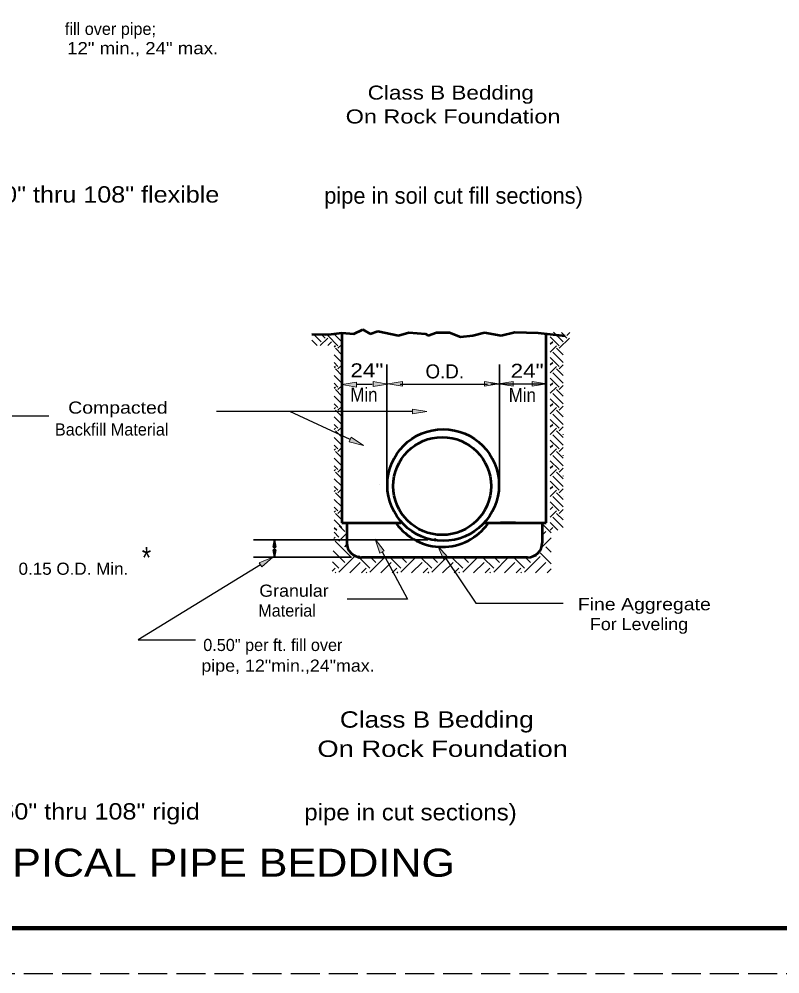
# Model space of a CAD drawing. Extents: x 36.1 to 71.5, y 0.2 to 22.2.
# Drawn here: x 44.21 to 52.56, y 0.21 to 10.68 of the extents above; entities that cross this region are included whole.
import ezdxf

# ---------------------------------------------------------------- set-up
doc = ezdxf.new("R2010")
doc.units = 0
doc.header["$LTSCALE"] = 0.053
doc.header["$PDMODE"] = 32
doc.header["$PDSIZE"] = 0.0265
doc.linetypes.add('LONG_DASHED', pattern=[7.5, 6, -1.5])
for name, color, linetype, lineweight in [('1', 7, 'Continuous', 35), ('3', 7, 'Continuous', 25), ('4', 7, 'Continuous', 35), ('6', 7, 'Continuous', 13)]:
    doc.layers.add(name, color=color, linetype=linetype, lineweight=lineweight)

msp = doc.modelspace()

# ---------------------------------------------------------------- hatches: boundary and pattern name
at = {"layer": '1'}
for points in [[(47.91383, 6.64717), (47.91383, 6.7005), (47.75383, 6.67383), (47.75383, 6.67383)], [(48.0985, 6.65275), (48.0985, 6.70608), (48.2585, 6.67942), (48.2585, 6.67942)], [(48.4185, 6.65508), (48.4185, 6.7085), (48.2585, 6.68183), (48.2585, 6.68183)], [(49.31708, 6.65508), (49.31708, 6.7085), (49.47708, 6.68183), (49.47708, 6.68183)], [(47.02833, 4.89192), (47.00167, 4.89192), (47.015, 4.97192), (47.015, 4.97192)], [(47.02833, 4.86225), (47.00167, 4.86225), (47.015, 4.78225), (47.015, 4.78225)]]:
    msp.add_hatch(color=256, dxfattribs=at).paths.add_polyline_path(points)
at = {"layer": '3'}
for points in [[(49.63242, 6.65633), (49.63242, 6.70967), (49.47242, 6.683), (49.47242, 6.683)], [(49.84042, 6.65633), (49.84042, 6.70967), (50.00042, 6.683), (50.00042, 6.683)], [(48.52717, 6.40533), (48.52717, 6.35192), (48.68717, 6.37867), (48.68717, 6.37867)], [(47.85717, 6.096), (47.83475, 6.04783), (47.99117, 6.00458), (47.99117, 6.00458)], [(48.17117, 4.827), (48.218, 4.85242), (48.1185, 4.9805), (48.1185, 4.9805)], [(48.87183, 4.75342), (48.91625, 4.78308), (48.80533, 4.90133), (48.80533, 4.90133)], [(46.84783, 4.72108), (46.87558, 4.67575), (46.99808, 4.78225), (46.99808, 4.78225)]]:
    msp.add_hatch(color=256, dxfattribs=at).paths.add_polyline_path(points)

# ---------------------------------------------------------------- linework, layer by layer
at = {"layer": '1', "lineweight": 53}
for p, q in [((47.42317, 7.225), (47.6065, 7.22233)), ((47.6065, 7.22233), (47.75383, 7.2425)), ((47.75383, 7.2425), (47.88425, 7.22883)), ((47.75383, 7.2425), (47.75383, 5.15825)), ((47.88425, 7.22883), (47.9825, 7.27642)), ((47.9825, 7.27642), (48.06558, 7.22883)), ((48.06558, 7.22883), (48.14867, 7.2605)), ((48.14867, 7.2605), (48.37533, 7.21292)), ((48.37533, 7.21292), (48.48875, 7.24458)), ((48.48875, 7.24458), (48.67008, 7.22883)), ((48.67008, 7.22883), (48.70025, 7.21292)), ((48.70025, 7.21292), (48.79092, 7.24458)), ((48.79092, 7.24458), (48.9345, 7.24458)), ((48.9345, 7.24458), (49.05533, 7.197)), ((49.19133, 7.21292), (49.31983, 7.24458)), ((49.31983, 7.24458), (49.50117, 7.21292)), ((49.50117, 7.21292), (49.65067, 7.24925)), ((49.65067, 7.24925), (49.907, 7.2425)), ((49.907, 7.2425), (50.20183, 7.20892)), ((49.99633, 5.15825), (49.99633, 7.23225)), ((49.05533, 7.197), (49.19133, 7.21292)), ((47.75383, 5.15825), (48.39975, 5.15825)), ((47.80833, 5.15825), (47.80833, 4.93975)), ((49.31333, 5.15825), (49.99633, 5.15825)), ((49.6585, 5.15825), (49.4935, 5.15825)), ((49.95133, 5.15825), (49.95133, 4.93975)), ((49.79133, 4.77975), (47.96833, 4.77975))]:
    msp.add_line(p, q, dxfattribs=at)
at = {"layer": '1'}
for p, q in [((48.24733, 5.64717), (48.24733, 6.8955)), ((49.48267, 5.64725), (49.48267, 6.89558)), ((50.04892, 5.04983), (49.95133, 5.14742)), ((47.72192, 5.001), (47.66817, 5.05475)), ((47.72192, 4.95858), (47.80833, 5.04492)), ((47.78558, 5.06467), (47.72458, 5.12558)), ((49.95133, 5.02425), (49.99183, 5.06467)), ((48.69583, 4.97192), (46.78458, 4.97192)), ((47.66492, 4.98633), (47.6795, 5.001)), ((47.84925, 4.78883), (47.6795, 4.95858)), ((49.94292, 4.88858), (50.04892, 4.99458)), ((47.015, 4.89192), (47.015, 4.86225)), ((47.78558, 4.72525), (47.6585, 4.85225)), ((47.78558, 4.89492), (47.80967, 4.91908)), ((47.84925, 4.83125), (47.85, 4.832)), ((50.04892, 4.71042), (49.92808, 4.83125)), ((50.04892, 4.83767), (49.99183, 4.89492)), ((47.86083, 4.78225), (46.78458, 4.78225)), ((47.72192, 4.66158), (47.65283, 4.73083)), ((47.72192, 4.61917), (47.89158, 4.78883)), ((47.84058, 4.61058), (47.95525, 4.72525)), ((48.06133, 4.66158), (47.94083, 4.78225)), ((48.06133, 4.61917), (48.22192, 4.77975)), ((48.125, 4.72525), (48.07042, 4.77975)), ((48.18008, 4.61058), (48.29475, 4.72525)), ((48.40075, 4.66158), (48.2825, 4.77975)), ((48.40075, 4.61917), (48.56142, 4.77975)), ((48.46442, 4.72525), (48.40983, 4.77975)), ((48.5195, 4.61058), (48.63417, 4.72525)), ((48.74017, 4.66158), (48.62192, 4.77975)), ((48.74017, 4.61917), (48.90083, 4.77975)), ((48.80383, 4.72525), (48.74917, 4.77975)), ((48.85883, 4.61058), (48.9735, 4.72525)), ((49.0795, 4.66158), (48.96142, 4.77975)), ((49.0795, 4.61917), (49.24017, 4.77975)), ((49.14325, 4.72525), (49.08858, 4.77975)), ((49.19825, 4.61058), (49.31292, 4.72525)), ((49.419, 4.66158), (49.30083, 4.77975)), ((49.419, 4.61917), (49.57958, 4.77975)), ((49.48267, 4.72525), (49.42808, 4.77975)), ((49.53767, 4.61058), (49.65233, 4.72525)), ((49.75842, 4.66158), (49.64017, 4.77975)), ((49.75842, 4.61917), (49.92808, 4.78883)), ((49.82208, 4.72525), (49.7675, 4.77975)), ((49.88567, 4.78883), (49.87258, 4.80192)), ((49.87717, 4.61058), (49.99183, 4.72525)), ((47.648, 4.63008), (47.6795, 4.66158)), ((47.68808, 4.61058), (47.6795, 4.61917)), ((47.96783, 4.61058), (48.019, 4.66158)), ((48.0275, 4.61058), (48.019, 4.61917)), ((48.30725, 4.61058), (48.35842, 4.66158)), ((48.36692, 4.61058), (48.35842, 4.61917)), ((48.64675, 4.61058), (48.69767, 4.66158)), ((48.70633, 4.61058), (48.69767, 4.61917)), ((48.98617, 4.61058), (49.03717, 4.66158)), ((49.04575, 4.61058), (49.03717, 4.61917)), ((49.3255, 4.61058), (49.3765, 4.66158)), ((49.38517, 4.61058), (49.3765, 4.61917)), ((49.66492, 4.61058), (49.71592, 4.66158)), ((49.72458, 4.61058), (49.71592, 4.61917)), ((50.00433, 4.61058), (50.04892, 4.65517))]:
    msp.add_line(p, q, dxfattribs=at)
at = {"layer": '1', "lineweight": 13}
msp.add_line((47.75383, 6.60183), (47.75383, 6.44342), dxfattribs=at)
at = {"layer": '1', "lineweight": 25}
for p, q in [((48.08758, 6.67383), (47.91383, 6.67383)), ((48.39417, 6.67683), (49.353, 6.67683))]:
    msp.add_line(p, q, dxfattribs=at)
at = {"layer": '1', "linetype": 'LONG_DASHED', "lineweight": 25}
msp.add_line((71.33717, 0.21317), (36.13717, 0.21317), dxfattribs=at)
at = {"layer": '1', "lineweight": 158}
msp.add_lwpolyline([(71.25383, 21.71317), (71.25383, 0.71317), (38.75383, 0.71317)], dxfattribs=at)
at = {"layer": '1', "lineweight": 13}
for points in [[(47.91383, 6.64717), (47.91383, 6.7005), (47.75383, 6.67383), (47.75383, 6.67383)], [(48.0985, 6.65275), (48.0985, 6.70608), (48.2585, 6.67942), (48.2585, 6.67942)], [(48.4185, 6.65508), (48.4185, 6.7085), (48.2585, 6.68183), (48.2585, 6.68183)], [(49.31708, 6.65508), (49.31708, 6.7085), (49.47708, 6.68183), (49.47708, 6.68183)]]:
    msp.add_lwpolyline(points, close=True, dxfattribs=at)
at = {"layer": '1'}
for points in [[(47.02833, 4.89192), (47.00167, 4.89192), (47.015, 4.97192), (47.015, 4.97192)], [(47.02833, 4.86225), (47.00167, 4.86225), (47.015, 4.78225), (47.015, 4.78225)]]:
    msp.add_lwpolyline(points, close=True, dxfattribs=at)
at = {"layer": '1', "lineweight": 53}
for centre, radius in [((48.86494, 5.57276), 0.61202), ((48.85386, 5.56167), 0.53646)]:
    msp.add_circle(centre, radius, dxfattribs=at)
for centre, radius, start, end in [((48.85464, 5.51487), 0.6208, 215.70389, 324.29611), ((47.96831, 4.93976), 0.16, 180, 270), ((49.79135, 4.93976), 0.16, 270, 0)]:
    msp.add_arc(centre, radius, start, end, dxfattribs=at)
at = {"layer": '3'}
for p, q in [((49.38783, 6.68233), (49.99633, 6.68233)), ((43.22292, 6.33283), (44.53925, 6.33283)), ((48.52717, 6.37867), (46.3785, 6.37867)), ((47.84592, 6.07192), (47.18475, 6.37867))]:
    msp.add_line(p, q, dxfattribs=at)
at = {"layer": '3', "lineweight": 13}
msp.add_line((49.65067, 6.67383), (49.65075, 6.67383), dxfattribs=at)
for points in [[(49.63242, 6.65633), (49.63242, 6.70967), (49.47242, 6.683), (49.47242, 6.683)], [(49.84042, 6.65633), (49.84042, 6.70967), (50.00042, 6.683), (50.00042, 6.683)], [(48.52717, 6.40533), (48.52717, 6.35192), (48.68717, 6.37867), (48.68717, 6.37867)], [(47.85717, 6.096), (47.83475, 6.04783), (47.99117, 6.00458), (47.99117, 6.00458)], [(48.17117, 4.827), (48.218, 4.85242), (48.1185, 4.9805), (48.1185, 4.9805)], [(48.87183, 4.75342), (48.91625, 4.78308), (48.80533, 4.90133), (48.80533, 4.90133)], [(46.84783, 4.72108), (46.87558, 4.67575), (46.99808, 4.78225), (46.99808, 4.78225)]]:
    msp.add_lwpolyline(points, close=True, dxfattribs=at)
at = {"layer": '3'}
for points in [[(48.19467, 4.83967), (48.475, 4.32142), (47.81283, 4.32142)], [(48.89408, 4.76825), (49.22192, 4.27692), (50.18117, 4.27692)], [(46.86167, 4.6985), (45.52125, 3.87625), (46.14933, 3.87625)]]:
    msp.add_lwpolyline(points, dxfattribs=at)
at = {"layer": '4'}
for p, q in [((47.52783, 7.14242), (47.4455, 7.22467)), ((47.57017, 7.18475), (47.53158, 7.22342)), ((47.75383, 7.14258), (47.666, 7.23042)), ((50.18017, 7.14242), (50.07417, 7.24833)), ((50.2225, 7.18475), (50.16125, 7.246)), ((50.2225, 7.213), (50.253, 7.24367)), ((47.48408, 7.10125), (47.42317, 7.16217)), ((47.515, 7.10125), (47.5985, 7.18475)), ((47.71167, 7.09992), (47.5985, 7.213)), ((47.59983, 7.10125), (47.64092, 7.14242)), ((50.13767, 7.09992), (50.04017, 7.19733)), ((50.04017, 7.11567), (50.067, 7.14242)), ((50.13767, 7.07167), (50.25075, 7.18475)), ((47.6705, 7.08717), (47.68325, 7.09992)), ((47.75383, 7.00125), (47.68325, 7.07167)), ((47.71167, 7.07167), (47.75383, 7.11383)), ((50.04017, 7.03075), (50.10942, 7.09992)), ((50.18017, 6.91608), (50.067, 7.02925)), ((50.18117, 6.99983), (50.10942, 7.07167)), ((50.18017, 7.02925), (50.18117, 7.03033)), ((47.75383, 6.91625), (47.6705, 6.99958)), ((47.71167, 6.87375), (47.6705, 6.91483)), ((50.13767, 6.87375), (50.04017, 6.97117)), ((50.04017, 6.88942), (50.067, 6.91608)), ((47.6705, 6.86083), (47.68325, 6.87375)), ((47.75383, 6.77492), (47.68325, 6.84533)), ((47.71167, 6.84533), (47.75383, 6.88758)), ((50.04017, 6.8045), (50.10942, 6.87375)), ((50.18117, 6.77358), (50.10942, 6.84533)), ((50.13767, 6.84533), (50.18117, 6.88892)), ((47.75383, 6.69008), (47.6705, 6.77333)), ((50.13767, 6.64742), (50.04017, 6.74492)), ((50.18017, 6.68983), (50.067, 6.803)), ((47.71167, 6.64742), (47.6705, 6.6885)), ((47.6705, 6.63458), (47.68325, 6.64742)), ((47.75383, 6.54858), (47.68325, 6.61917)), ((47.71167, 6.61917), (47.75383, 6.66133)), ((50.04017, 6.66308), (50.067, 6.68983)), ((50.04017, 6.57825), (50.10942, 6.64742)), ((50.18117, 6.54733), (50.10942, 6.61917)), ((50.13767, 6.61917), (50.18117, 6.66258)), ((47.75383, 6.46383), (47.6705, 6.54717)), ((50.13767, 6.42117), (50.04017, 6.51858)), ((50.18017, 6.46358), (50.067, 6.57667)), ((50.18017, 6.57667), (50.18117, 6.57783)), ((47.71167, 6.42117), (47.6705, 6.46225)), ((47.6705, 6.40833), (47.68325, 6.42117)), ((47.75383, 6.32233), (47.68325, 6.39292)), ((47.71167, 6.39292), (47.75383, 6.435)), ((50.04017, 6.43683), (50.067, 6.46358)), ((50.04017, 6.35192), (50.10942, 6.42117)), ((50.18117, 6.321), (50.10942, 6.39292)), ((50.13767, 6.39292), (50.18117, 6.43642)), ((47.75383, 6.2375), (47.6705, 6.32075)), ((50.13767, 6.19492), (50.04017, 6.29225)), ((50.18017, 6.23725), (50.067, 6.35042)), ((47.71167, 6.19492), (47.6705, 6.23592)), ((47.6705, 6.182), (47.68325, 6.19492)), ((47.71167, 6.16658), (47.75383, 6.20875)), ((50.04017, 6.21058), (50.067, 6.23725)), ((50.04017, 6.12567), (50.10942, 6.19492)), ((50.13767, 6.16658), (50.18117, 6.21017)), ((47.75383, 6.01125), (47.6705, 6.09458)), ((47.75383, 6.096), (47.68325, 6.16658)), ((50.18017, 6.011), (50.067, 6.12425)), ((50.18117, 6.09475), (50.10942, 6.16658)), ((50.18017, 6.12425), (50.18117, 6.12525)), ((47.71167, 5.96858), (47.6705, 6.00958)), ((47.6705, 5.95575), (47.68325, 5.96858)), ((47.71167, 5.94025), (47.75383, 5.98258)), ((50.13767, 5.96858), (50.04017, 6.06608)), ((50.04017, 5.98425), (50.067, 6.011)), ((50.04017, 5.89942), (50.10942, 5.96858)), ((50.13767, 5.94025), (50.18117, 5.98383)), ((47.75383, 5.785), (47.6705, 5.86825)), ((47.75383, 5.86983), (47.68325, 5.94025)), ((50.18017, 5.78475), (50.067, 5.89783)), ((50.18117, 5.8685), (50.10942, 5.94025)), ((50.18017, 5.89783), (50.18117, 5.899)), ((47.71167, 5.74233), (47.6705, 5.78342)), ((50.13767, 5.74233), (50.04017, 5.83967)), ((50.04017, 5.758), (50.067, 5.78475)), ((50.13767, 5.71408), (50.18117, 5.75758)), ((47.6705, 5.72958), (47.68325, 5.74233)), ((47.75383, 5.64358), (47.68325, 5.71408)), ((47.71167, 5.71408), (47.75383, 5.75625)), ((50.04017, 5.67325), (50.10942, 5.74233)), ((50.18017, 5.55842), (50.067, 5.67158)), ((50.18117, 5.64217), (50.10942, 5.71408)), ((50.18017, 5.67158), (50.18117, 5.67267)), ((47.75383, 5.55858), (47.6705, 5.64192)), ((47.71167, 5.51608), (47.6705, 5.55717)), ((50.13767, 5.51608), (50.04017, 5.6135)), ((50.04017, 5.53175), (50.067, 5.55842)), ((47.6705, 5.50325), (47.68325, 5.51608)), ((47.75383, 5.41725), (47.68325, 5.48767)), ((47.71167, 5.48767), (47.75383, 5.52992)), ((50.04017, 5.44692), (50.10942, 5.51608)), ((50.18017, 5.33225), (50.067, 5.44533)), ((50.18117, 5.41592), (50.10942, 5.48767)), ((50.13767, 5.48767), (50.18117, 5.53133)), ((50.18017, 5.44533), (50.18117, 5.44642)), ((47.75383, 5.33242), (47.6705, 5.41567)), ((50.13767, 5.28975), (50.04017, 5.38725)), ((47.71167, 5.28975), (47.6705, 5.33083)), ((47.6705, 5.27692), (47.68325, 5.28975)), ((47.75383, 5.19092), (47.68325, 5.2615)), ((47.71167, 5.2615), (47.75383, 5.30367)), ((50.04017, 5.30542), (50.067, 5.33225)), ((50.04017, 5.22058), (50.10942, 5.28975)), ((50.18117, 5.18967), (50.10942, 5.2615)), ((50.13767, 5.2615), (50.18117, 5.305)), ((47.754, 5.10592), (47.6705, 5.1895)), ((50.12358, 5.07758), (50.04017, 5.16092)), ((50.18017, 5.10592), (50.067, 5.219)), ((47.69758, 5.07758), (47.6705, 5.10458)), ((50.03858, 5.07758), (50.067, 5.10592))]:
    msp.add_line(p, q, dxfattribs=at)
at = {"layer": '4', "lineweight": 13}
for p, q in [((47.75383, 7.22742), (47.74058, 7.24067)), ((47.57017, 7.213), (47.57983, 7.22275)), ((50.18017, 6.803), (50.18117, 6.80408)), ((49.3645, 6.67792), (49.36458, 6.67792)), ((49.3645, 6.66592), (49.36458, 6.66592)), ((50.18017, 6.35042), (50.18117, 6.3515)), ((50.18017, 5.219), (50.18117, 5.22025))]:
    msp.add_line(p, q, dxfattribs=at)
at = {"layer": '6'}
for p, q in [((47.75383, 6.68183), (47.75392, 6.68183)), ((47.75383, 6.67383), (47.75392, 6.67383)), ((48.16375, 6.67383), (48.16383, 6.67383)), ((49.38783, 6.68183), (49.38792, 6.68183)), ((49.19475, 5.91808), (49.19483, 5.91808)), ((48.16375, 5.58392), (48.16383, 5.58392)), ((49.38783, 5.58392), (49.38792, 5.58392)), ((48.36617, 5.2365), (48.36625, 5.2365)), ((49.7385, 5.15825), (49.73867, 5.15825)), ((48.76008, 4.89967), (48.76017, 4.89967))]:
    msp.add_line(p, q, dxfattribs=at)
at = {"layer": '6', "lineweight": 35}
msp.add_line((47.015, 4.78225), (47.01517, 4.78225), dxfattribs=at)
at = {"layer": '6'}
for p in [(48.77583, 4.97192), (47.94083, 4.78225)]:
    msp.add_point(p, dxfattribs=at)

# ---------------------------------------------------------------- texts
at = {"layer": '1'}
msp.add_text('O.D.', height=0.1536, dxfattribs=at).set_placement((48.67142, 6.74183))
at = {"layer": '3'}
for s, height, p in [('fill over pipe;', 0.133, (44.71708, 10.5075)), ('pipe in soil cut fill sections)', 0.1792, (47.5605, 8.65708)), ('Backfill Material', 0.133, (44.60725, 6.1155)), ('Material', 0.133, (46.83675, 4.13033)), ('0.50" per ft. fill over', 0.133, (46.23417, 3.75292))]:
    msp.add_text(s, height=height, dxfattribs=at).set_placement(p)
for s, height, width, p in [('12" min., 24" max.', 0.133, 1.15, (44.74083, 10.29617)), ('Class B Bedding', 0.1536, 1.2, (48.03767, 9.79833)), ('On Rock Foundation', 0.1536, 1.25, (47.79617, 9.53667)), ('(Trench shown is for 60" thru 108" flexible', 0.1792, 1.15, (41.313, 8.66908)), ('24"', 0.1536, 1.2, (47.8475, 6.75333)), ('24"', 0.1536, 1.2, (49.605, 6.74808)), ('Min', 0.1536, 0.9, (47.84725, 6.48658)), ('Min', 0.1536, 0.9, (49.58433, 6.48133)), ('Compacted', 0.133, 1.2, (44.75258, 6.35533)), ('*', 0.2304, 0.85, (45.56083, 4.662)), ('0.15 O.D. Min.', 0.133, 1.05, (44.20817, 4.58892)), ('Granular', 0.133, 1.1, (46.84825, 4.34808)), ('Fine Aggregate', 0.133, 1.2, (50.34117, 4.20017)), ('For Leveling', 0.133, 1.1, (50.47458, 3.98167)), ('pipe, 12"min.,24"max.', 0.133, 1.1, (46.21342, 3.52642)), ('Class B Bedding', 0.1792, 1.2, (47.73208, 2.91275)), ('On Rock Foundation', 0.1792, 1.25, (47.48592, 2.59225)), ('(Trench shown is for 60" thru 108" rigid', 0.1792, 1.15, (41.43617, 1.9055)), ('pipe in cut sections)', 0.1792, 1.1, (47.342, 1.89675)), ('TYPICAL PIPE BEDDING', 0.3072, 1.15, (43.53475, 1.27883))]:
    msp.add_text(s, height=height, dxfattribs=dict(at, width=width)).set_placement(p)

doc.saveas('drawing.dxf')
